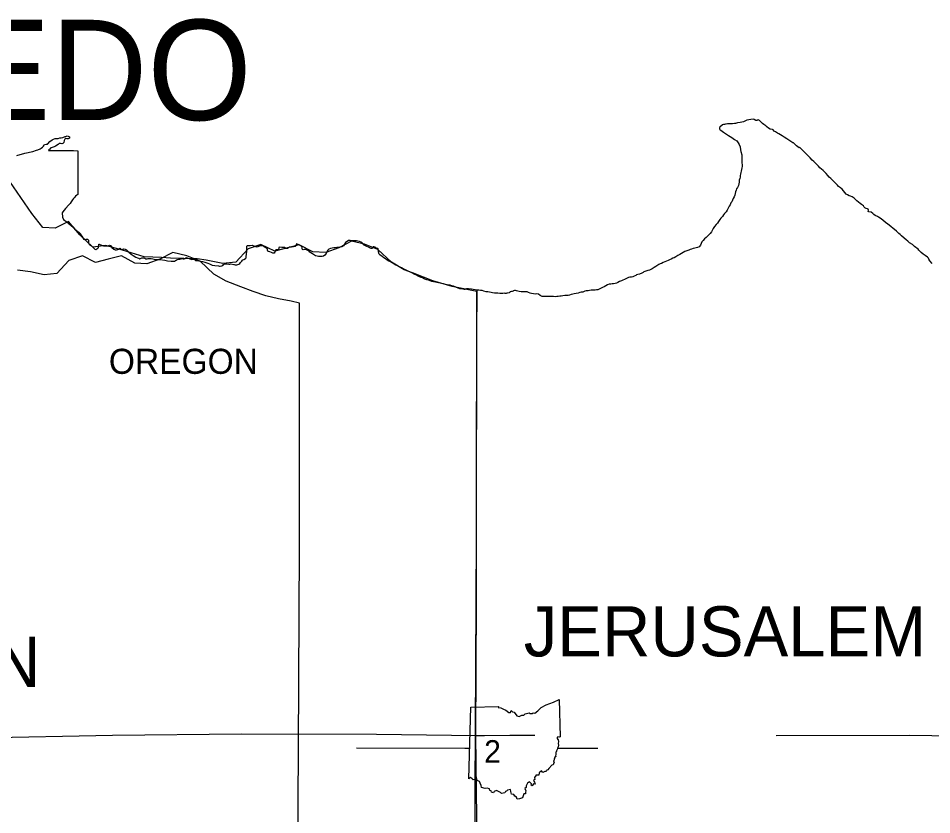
# Model space of a CAD drawing. Extents: x -232 to 448, y 619 to 1059.
# Drawn here: x 201.69 to 239.07, y 921.24 to 953.82 of the extents above; entities that cross this region are included whole.
import ezdxf

# ---------------------------------------------------------------- set-up
doc = ezdxf.new("R2010")
doc.units = 0
doc.layers.add('Default', color=7, linetype='Continuous')

msp = doc.modelspace()

# ---------------------------------------------------------------- linework, layer by layer
at = {"layer": 'Default'}
msp.add_line((220.126, 922.713), (220.208, 925.642), dxfattribs=at)
msp.add_line((220.126, 922.713), (220.208, 925.642), dxfattribs=at)
for points in [[(230.508, 949.458), (230.402, 949.373), (230.379, 949.341), (230.389, 949.297), (230.397, 949.276), (230.431, 949.244), (230.545, 949.165)], [(234.088, 948.119), (233.874, 948.332), (233.734, 948.47), (233.672, 948.541), (233.64, 948.519), (233.539, 948.609), (233.41, 948.732), (233.385, 948.722), (233.257, 948.815), (233.131, 948.893), (233.023, 948.964), (232.942, 949.013), (232.879, 949.057), (232.812, 949.091), (232.753, 949.125), (232.668, 949.171), (232.621, 949.201), (232.572, 949.257), (232.546, 949.27), (232.456, 949.285), (232.381, 949.334), (232.318, 949.386), (232.275, 949.42), (232.202, 949.476), (232.148, 949.522), (232.018, 949.642), (231.967, 949.675), (231.93, 949.649), (231.922, 949.645), (231.895, 949.635), (231.869, 949.642), (231.804, 949.684), (231.763, 949.693), (231.66, 949.684), (231.58, 949.675), (231.506, 949.657), (231.415, 949.62), (231.361, 949.592), (231.299, 949.574), (231.225, 949.554), (231.114, 949.54), (231.036, 949.522), (230.995, 949.515), (230.919, 949.51), (230.833, 949.507), (230.774, 949.506), (230.712, 949.498), (230.658, 949.491), (230.622, 949.489), (230.582, 949.484), (230.541, 949.472), (230.508, 949.458)], [(201.63, 948.204), (201.965, 948.298), (202.283, 948.378), (202.435, 948.425), (202.493, 948.443), (202.585, 948.487), (202.628, 948.512), (202.678, 948.546), (202.721, 948.591), (202.752, 948.638), (202.769, 948.663), (202.839, 948.671), (202.882, 948.675), (202.906, 948.693), (202.987, 948.776), (203.078, 948.85), (203.131, 948.878), (203.205, 948.9), (203.24, 948.902), (203.322, 948.899), (203.39, 948.934), (203.445, 948.927), (203.509, 948.939), (203.603, 948.982), (203.638, 948.981), (203.698, 949.008), (203.739, 948.995), (203.788, 948.968), (203.783, 948.919), (203.736, 948.89), (203.681, 948.897), (203.629, 948.903), (203.592, 948.873), (203.565, 948.828), (203.559, 948.746), (203.521, 948.705), (203.48, 948.692), (203.417, 948.701), (203.361, 948.696), (203.324, 948.657), (203.221, 948.594), (203.158, 948.563), (203.078, 948.541), (203.018, 948.519), (202.985, 948.474), (202.942, 948.442), (202.928, 948.416), (203.159, 948.415), (203.604, 948.408), (203.95, 948.407), (204.127, 948.404), (204.123, 947.88), (204.125, 947.249), (204.13, 946.608)], [(230.545, 949.165), (230.582, 949.142)], [(230.582, 949.142), (230.675, 949.081), (230.75, 949.029), (230.891, 948.95), (231, 948.869), (231.087, 948.803), (231.148, 948.728), (231.19, 948.658), (231.225, 948.557), (231.24, 948.447), (231.255, 948.373), (231.294, 948.237), (231.299, 948.107), (231.3, 948.035), (231.3, 947.895), (231.307, 947.837), (231.306, 947.765), (231.297, 947.702)], [(202.7, 945.257), (202.244, 945.831), (201.649, 946.715), (201.193, 947.367), (200.663, 947.789), (200.123, 948.22)], [(236.197, 946.204), (236.132, 946.252), (236.071, 946.298), (236, 946.359), (235.946, 946.409), (235.887, 946.465), (235.808, 946.512), (235.74, 946.542), (235.684, 946.563), (235.618, 946.599), (235.565, 946.633), (235.509, 946.695), (235.463, 946.76), (235.402, 946.826), (235.327, 946.893), (235.258, 946.944), (235.206, 946.994), (235.141, 947.065), (235.08, 947.132), (235.01, 947.205), (234.935, 947.272), (234.876, 947.326), (234.812, 947.395), (234.751, 947.466), (234.688, 947.534), (234.628, 947.589), (234.561, 947.647), (234.491, 947.709), (234.431, 947.769), (234.365, 947.836), (234.306, 947.898), (234.245, 947.957), (234.179, 948.021), (234.088, 948.119)], [(231.297, 947.702), (231.282, 947.63), (231.27, 947.564), (231.257, 947.507), (231.244, 947.443), (231.233, 947.39), (231.222, 947.324), (231.209, 947.267), (231.193, 947.197), (231.184, 947.119), (231.175, 947.045), (231.165, 946.975), (231.123, 946.906), (231.083, 946.841), (231.066, 946.787), (231.039, 946.718), (231.019, 946.65), (231.004, 946.58), (230.976, 946.519), (230.943, 946.45), (230.913, 946.382), (230.883, 946.319), (230.852, 946.266), (230.818, 946.196), (230.78, 946.131), (230.738, 946.06), (230.69, 945.976), (230.652, 945.907), (230.589, 945.838), (230.551, 945.778), (230.499, 945.711), (230.439, 945.642), (230.399, 945.587), (230.345, 945.514), (230.296, 945.443), (230.244, 945.386), (230.182, 945.307), (230.121, 945.223), (230.085, 945.141), (230.05, 945.082), (230.001, 945.019), (229.958, 944.971), (229.887, 944.914), (229.833, 944.853), (229.774, 944.802), (229.716, 944.737), (229.662, 944.682), (229.634, 944.613), (229.609, 944.537), (229.548, 944.478), (229.482, 944.444), (229.425, 944.429), (229.369, 944.417), (229.307, 944.402), (229.233, 944.38), (229.179, 944.358), (229.122, 944.334), (229.043, 944.313), (228.963, 944.277), (228.893, 944.237), (228.826, 944.197), (228.758, 944.163), (228.684, 944.117), (228.599, 944.064), (228.531, 944.024), (228.479, 944.006), (228.399, 943.969), (228.343, 943.946), (228.277, 943.913), (228.211, 943.885), (228.141, 943.855), (228.073, 943.827), (228.011, 943.797), (227.957, 943.773), (227.901, 943.75), (227.854, 943.722), (227.773, 943.672), (227.705, 943.623), (227.628, 943.57), (227.574, 943.544), (227.521, 943.516)], [(204.13, 946.608), (204.088, 946.585), (204.039, 946.551), (203.999, 946.498), (203.953, 946.446), (203.91, 946.391), (203.859, 946.307), (203.809, 946.244), (203.755, 946.185), (203.617, 946.038), (203.514, 945.903), (203.483, 945.864)], [(239.084, 943.795), (238.983, 943.897), (238.953, 943.962), (238.93, 944.011), (238.895, 944.047), (238.798, 944.12), (238.721, 944.169), (238.636, 944.242), (238.589, 944.284), (238.532, 944.342), (238.506, 944.378), (238.362, 944.489), (238.275, 944.564), (238.153, 944.638), (238.093, 944.698), (238.022, 944.755), (237.941, 944.824), (237.831, 944.918), (237.773, 944.977), (237.718, 945.017), (237.619, 945.107), (237.544, 945.178), (237.489, 945.224), (237.398, 945.303), (237.266, 945.404), (237.179, 945.473), (237.063, 945.557), (236.954, 945.649), (236.895, 945.693), (236.846, 945.717), (236.754, 945.751), (236.696, 945.795), (236.651, 945.841), (236.59, 945.895), (236.494, 945.905), (236.47, 945.924), (236.477, 945.971), (236.469, 946.014), (236.432, 946.029), (236.385, 946.042), (236.334, 946.07), (236.308, 946.099), (236.272, 946.151), (236.197, 946.204)], [(203.483, 945.864), (203.494, 945.687), (203.541, 945.597), (203.694, 945.48)], [(205.953, 944.342), (205.264, 944.524), (204.744, 944.456), (204.215, 944.968), (203.746, 945.503), (203.195, 945.23), (202.7, 945.257)], [(203.694, 945.48), (203.736, 945.445), (203.793, 945.399), (203.857, 945.347), (203.934, 945.275), (203.989, 945.205), (204.058, 945.151), (204.126, 945.105), (204.185, 945.055), (204.246, 944.987), (204.295, 944.906), (204.331, 944.838), (204.359, 944.791), (204.394, 944.768), (204.431, 944.764), (204.464, 944.784), (204.523, 944.79), (204.558, 944.744), (204.566, 944.695), (204.57, 944.631), (204.59, 944.584), (204.649, 944.54)], [(204.649, 944.54), (204.688, 944.517), (204.733, 944.47), (204.777, 944.414), (204.83, 944.372), (204.871, 944.368), (204.949, 944.415), (204.97, 944.449), (204.983, 944.499), (204.983, 944.538), (204.981, 944.566), (204.985, 944.577), (204.998, 944.587), (205.067, 944.551), (205.131, 944.524), (205.172, 944.514), (205.213, 944.511), (205.246, 944.515), (205.323, 944.513)], [(205.323, 944.513), (205.35, 944.514), (205.393, 944.527), (205.422, 944.539), (205.461, 944.532), (205.518, 944.443), (205.597, 944.371), (205.656, 944.35), (205.679, 944.346), (205.714, 944.35), (205.761, 944.359), (205.8, 944.374), (205.831, 944.402), (205.845, 944.416), (205.86, 944.398), (205.884, 944.361), (205.904, 944.36), (205.927, 944.366), (206.001, 944.384), (206.071, 944.378), (206.116, 944.351), (206.166, 944.305), (206.219, 944.251), (206.311, 944.166), (206.389, 944.119), (206.503, 944.048), (206.571, 944.021), (206.618, 944.006), (206.667, 943.987), (206.689, 944.001), (206.747, 944.022), (206.823, 944.019), (206.872, 944.006), (206.917, 943.986), (206.96, 943.983), (207.009, 943.993), (207.064, 943.999), (207.128, 943.994), (207.2, 943.985), (207.253, 943.966), (207.302, 943.957), (207.364, 943.953), (207.486, 943.948)], [(213.182, 944.558), (212.185, 944.296), (211.619, 944.564), (211.1, 944.389), (210.588, 943.849), (210.06, 943.795), (209.382, 943.929), (209.007, 943.978), (207.926, 944.013), (207.545, 944.041), (206.844, 944.059), (205.953, 944.342)], [(209.329, 943.847), (209.452, 943.811), (209.519, 943.771), (209.625, 943.719), (209.732, 943.704), (209.877, 943.701), (209.92, 943.682), (209.945, 943.684), (210.019, 943.696), (210.056, 943.708), (210.091, 943.745), (210.124, 943.773), (210.218, 943.775), (210.302, 943.762), (210.345, 943.757), (210.392, 943.771), (210.517, 943.756), (210.521, 943.756), (210.566, 943.739), (210.64, 943.737), (210.714, 943.769), (210.761, 943.795), (210.78, 943.828), (210.844, 943.889), (210.859, 943.924), (210.869, 943.939), (210.918, 943.953), (210.982, 943.989), (211.013, 944.026), (211.019, 944.071), (211.039, 944.283), (211.038, 944.404), (211.049, 944.503), (211.071, 944.532), (211.184, 944.528), (211.266, 944.538), (211.328, 944.517), (211.397, 944.488), (211.442, 944.477), (211.502, 944.485), (211.531, 944.499), (211.578, 944.522), (211.672, 944.521)], [(213.594, 944.293), (213.518, 944.337), (213.455, 944.364), (213.391, 944.365), (213.348, 944.353), (213.323, 944.361), (213.311, 944.394), (213.308, 944.437), (213.287, 944.487), (213.23, 944.528), (213.142, 944.572), (213.077, 944.591), (213.062, 944.558), (213.054, 944.517), (213.035, 944.497), (213.025, 944.484), (212.949, 944.473), (212.873, 944.465), (212.793, 944.453), (212.746, 944.435), (212.705, 944.409), (212.655, 944.405), (212.619, 944.42), (212.578, 944.442), (212.527, 944.449), (212.471, 944.445), (212.395, 944.456), (212.346, 944.45), (212.339, 944.35), (212.235, 944.35), (212.214, 944.309), (212.195, 944.25), (212.156, 944.217), (212.103, 944.216), (212.052, 944.236), (211.98, 944.262), (211.929, 944.278), (211.904, 944.301), (211.892, 944.336), (211.882, 944.386), (211.827, 944.425), (211.788, 944.444), (211.752, 944.469), (211.729, 944.498), (211.672, 944.521)], [(220.456, 942.644), (219.439, 942.853), (218.66, 943.087), (217.825, 943.402), (217.487, 943.538), (216.956, 943.844), (216.403, 944.365), (215.857, 944.579), (215.327, 944.701), (214.81, 944.436), (214.274, 944.24), (213.741, 944.268), (213.182, 944.558)], [(215.65, 944.688), (215.585, 944.705), (215.529, 944.717), (215.474, 944.722), (215.409, 944.718), (215.333, 944.715), (215.275, 944.725), (215.206, 944.732), (215.142, 944.696), (215.08, 944.649), (215.045, 944.581), (215.003, 944.511), (214.933, 944.475), (214.876, 944.465), (214.853, 944.461), (214.792, 944.447), (214.722, 944.442), (214.66, 944.432), (214.605, 944.428), (214.533, 944.42), (214.468, 944.4), (214.402, 944.374), (214.344, 944.321), (214.311, 944.259), (214.284, 944.194), (214.236, 944.126)], [(215.871, 944.528), (215.838, 944.543), (215.811, 944.554), (215.797, 944.568), (215.787, 944.594), (215.779, 944.623), (215.746, 944.648), (215.718, 944.665), (215.65, 944.688)], [(216.026, 944.455), (215.956, 944.492), (215.871, 944.528)], [(213.201, 942.169), (212.859, 942.244), (212.337, 942.339), (211.819, 942.469), (211.307, 942.641), (210.794, 942.832), (210.201, 943.07), (209.695, 943.359), (209.13, 943.892), (208.582, 944.109), (208.021, 944.239), (207.484, 943.965), (206.958, 943.772), (206.455, 943.802), (205.912, 944.102), (205.363, 943.969), (204.856, 943.825), (204.322, 944.103), (203.758, 943.913), (203.264, 943.381), (202.746, 943.329), (202.196, 943.448), (201.664, 943.519)], [(213.853, 944.109), (213.73, 944.185), (213.626, 944.257), (213.594, 944.293)], [(214.236, 944.126), (214.175, 944.09), (214.119, 944.074), (214.051, 944.072), (213.982, 944.077), (213.914, 944.09), (213.853, 944.109)], [(216.485, 944.143), (216.463, 944.174), (216.449, 944.211), (216.445, 944.236), (216.433, 944.259), (216.429, 944.296), (216.419, 944.347), (216.413, 944.372), (216.41, 944.391), (216.403, 944.399), (216.378, 944.401), (216.352, 944.403), (216.341, 944.418), (216.325, 944.436), (216.276, 944.453), (216.233, 944.466), (216.213, 944.47), (216.204, 944.443), (216.19, 944.419), (216.169, 944.409), (216.136, 944.411), (216.104, 944.423), (216.067, 944.436), (216.026, 944.455)], [(219.762, 942.759), (219.695, 942.776), (219.625, 942.803), (219.568, 942.834), (219.499, 942.862), (219.429, 942.879), (219.36, 942.898), (219.306, 942.91), (219.239, 942.913), (219.166, 942.926), (219.095, 942.953), (219.026, 942.978), (218.96, 942.989), (218.887, 943.002), (218.821, 943.017), (218.758, 943.033), (218.684, 943.042), (218.612, 943.061), (218.547, 943.084), (218.477, 943.111), (218.406, 943.126), (218.329, 943.155), (218.277, 943.179), (218.224, 943.2), (218.171, 943.219), (218.111, 943.246), (218.056, 943.279), (217.983, 943.314), (217.913, 943.344), (217.766, 943.419), (217.705, 943.454), (217.649, 943.479), (217.586, 943.508), (217.508, 943.544), (217.445, 943.569), (217.367, 943.613), (217.292, 943.648), (217.21, 943.69), (217.134, 943.726), (217.065, 943.767), (216.994, 943.815), (216.922, 943.859), (216.855, 943.892), (216.785, 943.929), (216.716, 943.975), (216.646, 944.023), (216.577, 944.075), (216.485, 944.143)], [(207.486, 943.948), (207.686, 943.921), (207.797, 943.903), (207.945, 943.892)], [(207.945, 943.892), (208.021, 943.885), (208.085, 943.889), (208.13, 943.915), (208.153, 943.933), (208.19, 943.949)], [(208.19, 943.949), (208.242, 943.962), (208.296, 943.967)], [(208.296, 943.967), (208.331, 943.975), (208.358, 943.987), (208.407, 943.993), (208.438, 943.981), (208.483, 943.98), (208.524, 943.996), (208.547, 944.019), (208.569, 944.037), (208.645, 944.012), (208.715, 943.979), (208.774, 943.96), (208.887, 943.967), (208.901, 943.969), (208.923, 943.928), (208.942, 943.913), (209.007, 943.907)], [(209.007, 943.907), (209.14, 943.888), (209.225, 943.869), (209.329, 943.847)], [(227.143, 943.368), (227.112, 943.358), (227.036, 943.336), (226.991, 943.321), (226.962, 943.298)], [(227.286, 943.444), (227.261, 943.422), (227.173, 943.378), (227.143, 943.368)], [(227.372, 943.477), (227.333, 943.462), (227.286, 943.444)], [(227.521, 943.516), (227.445, 943.505), (227.372, 943.477)], [(226.962, 943.298), (226.894, 943.266), (226.83, 943.245), (226.776, 943.231), (226.719, 943.226), (226.661, 943.216), (226.601, 943.193), (226.546, 943.167), (226.494, 943.136), (226.424, 943.107), (226.366, 943.085), (226.296, 943.051), (226.223, 943.009), (226.17, 942.989), (226.116, 942.973), (226.046, 942.96), (225.993, 942.955), (225.935, 942.951), (225.871, 942.94), (225.802, 942.914), (225.729, 942.874), (225.659, 942.838), (225.597, 942.806), (225.543, 942.78), (225.461, 942.738), (225.405, 942.72), (225.354, 942.709), (225.3, 942.703), (225.212, 942.701), (225.136, 942.7), (225.062, 942.688), (225.003, 942.679), (224.929, 942.672), (224.867, 942.66), (224.795, 942.62), (224.723, 942.615), (224.667, 942.604), (224.595, 942.576), (224.513, 942.559), (224.439, 942.547), (224.387, 942.536), (224.319, 942.518), (224.241, 942.497), (224.184, 942.487), (224.12, 942.486), (224.054, 942.479), (223.978, 942.47), (223.908, 942.458), (223.849, 942.449), (223.777, 942.44), (223.723, 942.436), (223.658, 942.433), (223.592, 942.434), (223.535, 942.439), (223.461, 942.447), (223.377, 942.444), (223.305, 942.445), (223.24, 942.439), (223.186, 942.44), (223.121, 942.447), (223.047, 942.475), (222.98, 942.53), (222.909, 942.545), (222.837, 942.54), (222.767, 942.551), (222.696, 942.567), (222.635, 942.576), (222.563, 942.6), (222.508, 942.627), (222.334, 942.628), (222.262, 942.633), (222.191, 942.642), (222.078, 942.671)], [(220.232, 942.735), (220.119, 942.75), (220.027, 942.755), (219.986, 942.737), (219.967, 942.723), (219.932, 942.723), (219.879, 942.734), (219.762, 942.759)], [(220.461, 942.705), (220.387, 942.713), (220.308, 942.73), (220.232, 942.735)], [(220.494, 917.745), (220.412, 924.484), (220.44, 929.941), (220.445, 935.396), (220.451, 940.914), (220.461, 942.705)], [(220.454, 938.128), (220.456, 942.644)], [(220.744, 942.66), (220.678, 942.683), (220.603, 942.691), (220.533, 942.7), (220.461, 942.705)], [(220.972, 942.619), (220.903, 942.632), (220.835, 942.633), (220.744, 942.66)], [(221.524, 942.566), (221.463, 942.565), (221.39, 942.57), (221.316, 942.581), (221.24, 942.58), (221.179, 942.581), (221.099, 942.584), (221.042, 942.599), (220.972, 942.619)], [(221.819, 942.625), (221.777, 942.597), (221.706, 942.579)], [(222.078, 942.671), (222.035, 942.681), (221.99, 942.688), (221.955, 942.67), (221.934, 942.656), (221.899, 942.644), (221.867, 942.647), (221.834, 942.637), (221.819, 942.625)], [(221.706, 942.579), (221.675, 942.572), (221.656, 942.57), (221.615, 942.566), (221.58, 942.571), (221.524, 942.566)], [(213.121, 917.175), (213.159, 923.975), (213.195, 932.178), (213.198, 937.62), (213.201, 942.169)], [(220.43, 929.912), (220.437, 932.67), (220.445, 935.834), (220.454, 938.128)], [(220.376, 919.589), (220.43, 929.912)], [(220.208, 925.642), (221.344, 925.661), (221.326, 925.626), (221.434, 925.618), (221.547, 925.556), (221.644, 925.516), (221.762, 925.423), (221.832, 925.424), (221.862, 925.501), (221.916, 925.442), (221.98, 925.431), (222.091, 925.291), (222.182, 925.261), (222.292, 925.309), (222.374, 925.317), (222.433, 925.364), (222.589, 925.405), (222.633, 925.38), (222.715, 925.385), (222.757, 925.403), (222.829, 925.387), (222.956, 925.494), (223.086, 925.619), (223.287, 925.738), (223.587, 925.85), (223.824, 925.95), (223.858, 924.43)], [(220.208, 925.642), (221.344, 925.661), (221.326, 925.626), (221.434, 925.618), (221.547, 925.556), (221.644, 925.516), (221.762, 925.423), (221.832, 925.424), (221.862, 925.501), (221.916, 925.442), (221.98, 925.431), (222.091, 925.291), (222.182, 925.261), (222.292, 925.309), (222.374, 925.317), (222.433, 925.364), (222.589, 925.405), (222.633, 925.38), (222.715, 925.385), (222.757, 925.403), (222.829, 925.387), (222.956, 925.494), (223.086, 925.619), (223.287, 925.738), (223.587, 925.85), (223.824, 925.95), (223.858, 924.43)], [(194.747, 924.352), (200.06, 924.388), (205.542, 924.488), (210.818, 924.547)], [(210.818, 924.547), (216.345, 924.537), (220.438, 924.486)], [(220.438, 924.486), (220.493, 924.485)], [(220.493, 924.485), (220.575, 924.484), (220.766, 924.485)], [(220.766, 924.485), (221.803, 924.49), (222.831, 924.488)], [(223.858, 924.43), (223.823, 924.409), (223.768, 924.419), (223.732, 924.376), (223.777, 924.305), (223.799, 924.23), (223.78, 924.147), (223.798, 924.079), (223.786, 924.022), (223.751, 923.965), (223.74, 923.911), (223.711, 923.854), (223.713, 923.822), (223.685, 923.796), (223.69, 923.701), (223.676, 923.648), (223.681, 923.603), (223.636, 923.591), (223.646, 923.554), (223.618, 923.525), (223.624, 923.475), (223.591, 923.443), (223.623, 923.379), (223.598, 923.359), (223.577, 923.281), (223.519, 923.266), (223.403, 923.124), (223.362, 923.07), (223.317, 923.057), (223.291, 923.002), (223.235, 923.001), (223.15, 922.963), (223.095, 923.029), (222.998, 922.95), (222.987, 922.859), (222.864, 922.862), (222.869, 922.815), (222.842, 922.802), (222.817, 922.756), (222.831, 922.673), (222.774, 922.653), (222.781, 922.605), (222.818, 922.576), (222.834, 922.484), (222.773, 922.503), (222.723, 922.426), (222.672, 922.444), (222.689, 922.509), (222.602, 922.587), (222.521, 922.525), (222.478, 922.425), (222.477, 922.357), (222.416, 922.316), (222.455, 922.221), (222.448, 922.156), (222.449, 922.093), (222.373, 922.095), (222.327, 921.927)], [(223.858, 924.43), (223.823, 924.409), (223.768, 924.419), (223.732, 924.376), (223.777, 924.305), (223.799, 924.23), (223.78, 924.147), (223.798, 924.079), (223.786, 924.022), (223.751, 923.965), (223.74, 923.911), (223.711, 923.854), (223.713, 923.822), (223.685, 923.796), (223.69, 923.701), (223.676, 923.648), (223.681, 923.603), (223.636, 923.591), (223.646, 923.554), (223.618, 923.525), (223.624, 923.475), (223.591, 923.443), (223.623, 923.379), (223.598, 923.359), (223.577, 923.281), (223.519, 923.266), (223.403, 923.124), (223.362, 923.07), (223.317, 923.057), (223.291, 923.002), (223.235, 923.001), (223.15, 922.963), (223.095, 923.029), (222.998, 922.95), (222.987, 922.859), (222.864, 922.862), (222.869, 922.815), (222.842, 922.802), (222.817, 922.756), (222.831, 922.673), (222.774, 922.653), (222.781, 922.605), (222.818, 922.576), (222.834, 922.484), (222.773, 922.503), (222.723, 922.426), (222.672, 922.444), (222.689, 922.509), (222.602, 922.587), (222.521, 922.525), (222.478, 922.425), (222.477, 922.357), (222.416, 922.316), (222.455, 922.221), (222.448, 922.156), (222.449, 922.093), (222.373, 922.095), (222.327, 921.927)], [(232.702, 924.475), (238.168, 924.488), (240.852, 924.449), (243.615, 924.478), (243.626, 924.477)], [(215.53, 923.971), (219.965, 923.961), (220.161, 923.961)], [(223.75, 923.959), (225.401, 923.958)], [(222.327, 921.927), (222.194, 921.895), (222.102, 921.876), (222.07, 921.952), (222.004, 921.992), (221.961, 922.069), (221.867, 922.08), (221.844, 922.185), (221.834, 922.271), (221.704, 922.25), (221.669, 922.198), (221.623, 922.184), (221.596, 922.131), (221.534, 922.126), (221.467, 922.101), (221.423, 922.153), (221.313, 922.205), (221.264, 922.232), (221.161, 922.19), (221.138, 922.141), (221.056, 922.163), (221.037, 922.218), (220.987, 922.234), (220.976, 922.293), (220.87, 922.324), (220.789, 922.311), (220.645, 922.358), (220.636, 922.435), (220.588, 922.529), (220.562, 922.594), (220.471, 922.643), (220.453, 922.72), (220.424, 922.718), (220.398, 922.687), (220.297, 922.672), (220.257, 922.704), (220.2, 922.758), (220.126, 922.713)], [(222.327, 921.927), (222.194, 921.895), (222.102, 921.876), (222.07, 921.952), (222.004, 921.992), (221.961, 922.069), (221.867, 922.08), (221.844, 922.185), (221.834, 922.271), (221.704, 922.25), (221.669, 922.198), (221.623, 922.184), (221.596, 922.131), (221.534, 922.126), (221.467, 922.101), (221.423, 922.153), (221.313, 922.205), (221.264, 922.232), (221.161, 922.19), (221.138, 922.141), (221.056, 922.163), (221.037, 922.218), (220.987, 922.234), (220.976, 922.293), (220.87, 922.324), (220.789, 922.311), (220.645, 922.358), (220.636, 922.435), (220.588, 922.529), (220.562, 922.594), (220.471, 922.643), (220.453, 922.72), (220.424, 922.718), (220.398, 922.687), (220.297, 922.672), (220.257, 922.704), (220.2, 922.758), (220.126, 922.713)]]:
    msp.add_lwpolyline(points, dxfattribs=at)

# ---------------------------------------------------------------- texts
for s, height, p in [('TOLEDO', 4.104, (188.679, 949.658)), ('OREGON', 1.026, (205.397, 939.276)), ('JERUSALEM', 2.052, (222.373, 927.715)), ('OREGON', 2.052, (190.4, 926.471)), (' 2 ', 0.9234, (220.408, 923.366))]:
    msp.add_text(s, height=height, dxfattribs=at).set_placement(p)

doc.saveas('drawing.dxf')
